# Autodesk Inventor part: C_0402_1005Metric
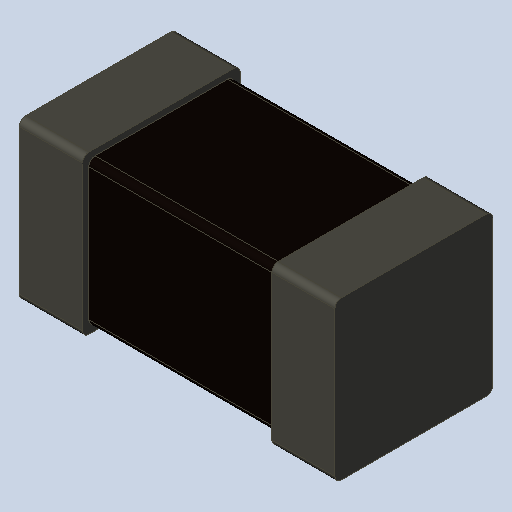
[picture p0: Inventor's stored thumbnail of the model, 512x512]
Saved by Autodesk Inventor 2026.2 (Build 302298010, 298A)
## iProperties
Created: 2026-10
Part Number: C_0402_1005Metric
Material: Générique
Document SubType Name: Modeling
Designer: mel
Density: 1 g/cm^3
Appearance: Par défaut
Author: mel
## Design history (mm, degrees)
feature "Base1"
node "Solide1"
